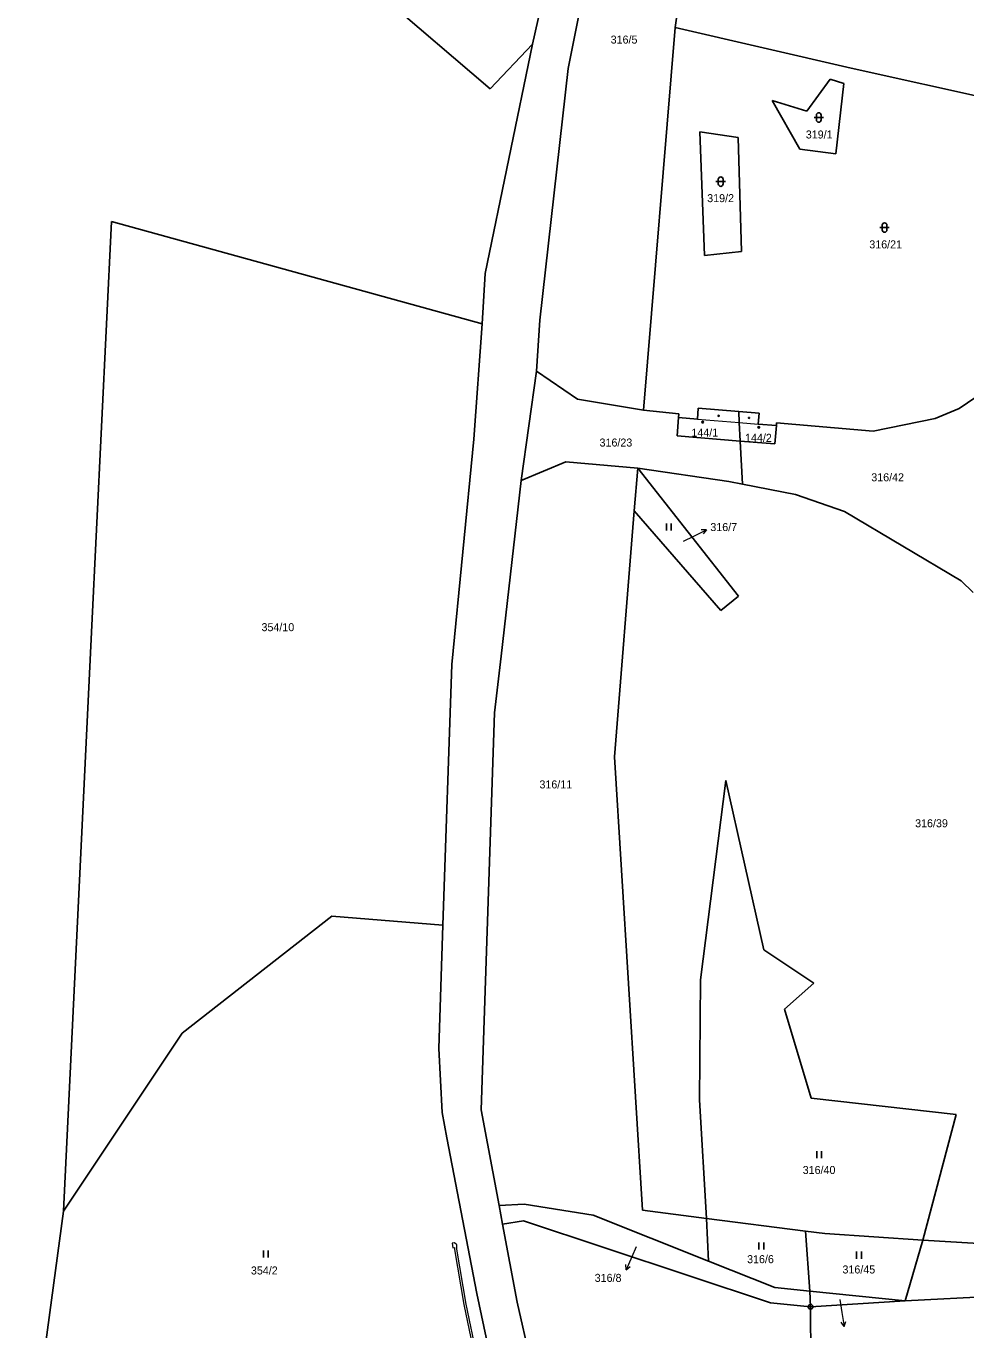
# Model space of a CAD drawing. Extents: x -765428 to -762163, y -1107632 to -1104975.
# Drawn here: x -764025.7 to -763826.2, y -1107138 to -1106861.1 of the extents above; entities that cross this region are included whole.
import ezdxf
from ezdxf.enums import TextEntityAlignment as Align

# ---------------------------------------------------------------- set-up
doc = ezdxf.new("R2010")
doc.units = 0
doc.header["$LTSCALE"] = 0.68
for name, color, linetype, lineweight in [('1', 7, 'Continuous', 25), ('13', 7, 'Continuous', 13), ('3', 7, 'Continuous', 25), ('4', 7, 'Continuous', 13), ('5', 7, 'Continuous', 25), ('7', 7, 'Continuous', 13), ('8', 7, 'Continuous', 25)]:
    doc.layers.add(name, color=color, linetype=linetype, lineweight=lineweight)
doc.layers.add('2', color=7, linetype='Continuous')

msp = doc.modelspace()

# ---------------------------------------------------------------- linework, layer by layer
at = {"layer": '1'}
for p, q in [((-763887.93, -1106861.4), (-763878.91, -1106800.35)), ((-763910.6, -1106870.13), (-763900.2, -1106816.93)), ((-763984.36, -1106825.5), (-763927.16, -1106874.4)), ((-763918.21, -1106864.97), (-763911.84, -1106836.29)), ((-763887.93, -1106861.4), (-763894.66, -1106942.69)), ((-763850.56, -1106870), (-763887.93, -1106861.4)), ((-763928.25, -1106913.64), (-763918.21, -1106864.97)), ((-763927.16, -1106874.4), (-763918.21, -1106864.97)), ((-763916.66, -1106923.52), (-763910.6, -1106870.13)), ((-763859.99, -1106879.13), (-763855, -1106872.34)), ((-763855, -1106872.34), (-763852.07, -1106873.28)), ((-763805.23, -1106880.1), (-763850.56, -1106870)), ((-763852.07, -1106873.28), (-763853.8, -1106888.22)), ((-763867.35, -1106876.88), (-763859.99, -1106879.13)), ((-763861.47, -1106887.23), (-763867.35, -1106876.88)), ((-763881.72, -1106909.85), (-763882.71, -1106883.52)), ((-763882.71, -1106883.52), (-763874.56, -1106884.77)), ((-763874.56, -1106884.77), (-763873.83, -1106908.96)), ((-763853.8, -1106888.22), (-763861.47, -1106887.23)), ((-764007.56, -1106902.63), (-764011.8, -1106989.83)), ((-764007.56, -1106902.63), (-763928.92, -1106924.36)), ((-763873.83, -1106908.96), (-763881.72, -1106909.85)), ((-763928.92, -1106924.36), (-763928.25, -1106913.64)), ((-763930.69, -1106948.85), (-763928.92, -1106924.36)), ((-763917.36, -1106934.4), (-763916.66, -1106923.52)), ((-763917.36, -1106934.4), (-763920.58, -1106957.6)), ((-763917.36, -1106934.4), (-763908.66, -1106940.29)), ((-763827.64, -1106942.32), (-763822.07, -1106938.55)), ((-763908.66, -1106940.29), (-763894.66, -1106942.69)), ((-763894.66, -1106942.69), (-763887.11, -1106943.42)), ((-763887.19, -1106944.24), (-763887.51, -1106948.1)), ((-763887.11, -1106943.42), (-763887.19, -1106944.24)), ((-763883.2, -1106944.57), (-763887.19, -1106944.24)), ((-763883.01, -1106942.25), (-763883.2, -1106944.57)), ((-763874.42, -1106942.97), (-763883.01, -1106942.25)), ((-763874.42, -1106942.97), (-763874.3, -1106945.31)), ((-763870.06, -1106943.33), (-763874.42, -1106942.97)), ((-763870.26, -1106945.65), (-763870.06, -1106943.33)), ((-763845.87, -1106947.12), (-763832.71, -1106944.44)), ((-763832.71, -1106944.44), (-763827.64, -1106942.32)), ((-763874.3, -1106945.31), (-763874.09, -1106949.21)), ((-763866.42, -1106945.95), (-763870.26, -1106945.65)), ((-763866.75, -1106949.81), (-763866.42, -1106945.95)), ((-763866.42, -1106945.95), (-763866.39, -1106945.32)), ((-763866.39, -1106945.32), (-763845.87, -1106947.12)), ((-763935.35, -1106996.66), (-763930.69, -1106948.85)), ((-763887.51, -1106948.1), (-763874.09, -1106949.21)), ((-763874.09, -1106949.21), (-763873.61, -1106958.36)), ((-763874.09, -1106949.21), (-763866.75, -1106949.81)), ((-763920.58, -1106957.6), (-763911.13, -1106953.64)), ((-763911.13, -1106953.64), (-763895.87, -1106954.97)), ((-763895.87, -1106954.97), (-763896.6, -1106964.04)), ((-763895.87, -1106954.97), (-763876.52, -1106957.78)), ((-763895.87, -1106954.97), (-763874.49, -1106982.19)), ((-763924.85, -1106994.91), (-763920.58, -1106957.6)), ((-763873.61, -1106958.36), (-763876.52, -1106957.78)), ((-763873.61, -1106958.36), (-763862.36, -1106960.58)), ((-763862.36, -1106960.58), (-763851.98, -1106964.19)), ((-763896.6, -1106964.04), (-763900.81, -1107016.28)), ((-763878.25, -1106985.17), (-763896.6, -1106964.04)), ((-763851.98, -1106964.19), (-763827.21, -1106978.88)), ((-763827.21, -1106978.88), (-763824.64, -1106981.35)), ((-763874.49, -1106982.19), (-763878.25, -1106985.17)), ((-764011.8, -1106989.83), (-764017.78, -1107112.73)), ((-763937.22, -1107052.04), (-763935.35, -1106996.66)), ((-763926.24, -1107006.92), (-763924.85, -1106994.91)), ((-763929.11, -1107091.25), (-763926.24, -1107006.92)), ((-763900.81, -1107016.28), (-763894.83, -1107112.58)), ((-763992.59, -1107074.99), (-763960.81, -1107050.1)), ((-763960.81, -1107050.1), (-763937.22, -1107052.04)), ((-763938.1, -1107078.21), (-763937.22, -1107052.04)), ((-763869.12, -1107057.24), (-763858.45, -1107064.32)), ((-763882.77, -1107089.12), (-763882.57, -1107063.6)), ((-763858.45, -1107064.32), (-763864.71, -1107069.87)), ((-763864.71, -1107069.87), (-763859.02, -1107088.76)), ((-764017.78, -1107112.73), (-763992.59, -1107074.99)), ((-763937.37, -1107091.79), (-763938.1, -1107078.21)), ((-763881.28, -1107114.32), (-763882.77, -1107089.12)), ((-763859.02, -1107088.76), (-763828.23, -1107092.25)), ((-763937.37, -1107091.79), (-763936.4, -1107097.18)), ((-763925.31, -1107111.55), (-763929.11, -1107091.25)), ((-763828.23, -1107092.25), (-763835.36, -1107118.94)), ((-763936.4, -1107097.18), (-763930.05, -1107130.21)), ((-764025.72, -1107171.67), (-764017.78, -1107112.73)), ((-763919.97, -1107111.24), (-763925.31, -1107111.55)), ((-763924.56, -1107115.5), (-763925.31, -1107111.55)), ((-763905.3, -1107113.6), (-763919.97, -1107111.24)), ((-763881.28, -1107114.32), (-763894.83, -1107112.58)), ((-763920.12, -1107114.79), (-763924.56, -1107115.5)), ((-763924.56, -1107115.5), (-763921.49, -1107132.12)), ((-763867.69, -1107132.24), (-763920.12, -1107114.79)), ((-763880.87, -1107123.35), (-763905.3, -1107113.6)), ((-763881.28, -1107114.32), (-763880.87, -1107123.35)), ((-763860.26, -1107116.98), (-763881.28, -1107114.32)), ((-763856.14, -1107117.5), (-763860.26, -1107116.98)), ((-763859.32, -1107129.72), (-763860.26, -1107116.98)), ((-763835.36, -1107118.94), (-763856.14, -1107117.5)), ((-763839.06, -1107131.83), (-763835.36, -1107118.94)), ((-763797.19, -1107121.2), (-763835.36, -1107118.94)), ((-763880.87, -1107123.35), (-763866.76, -1107128.95)), ((-763866.76, -1107128.95), (-763859.32, -1107129.72)), ((-763859.17, -1107133.06), (-763859.32, -1107129.72)), ((-763859.32, -1107129.72), (-763839.06, -1107131.83)), ((-763930.05, -1107130.21), (-763921.17, -1107171.3)), ((-763921.49, -1107132.12), (-763913.75, -1107165.7)), ((-763859.17, -1107133.06), (-763867.69, -1107132.24)), ((-763839.06, -1107131.83), (-763859.17, -1107133.06)), ((-763839.06, -1107131.83), (-763818, -1107130.74)), ((-763859.17, -1107133.06), (-763858.99, -1107159.24))]:
    msp.add_line(p, q, dxfattribs=at)
msp.add_lwpolyline([(-763882.57, -1107063.6), (-763877.13, -1107021.31), (-763869.12, -1107057.24)], dxfattribs=at)
at = {"layer": '13'}
msp.add_lwpolyline([(-763920.07, -1107191.01), (-763923.64, -1107173.12), (-763927.61, -1107154.9), (-763932.27, -1107132.51), (-763934.28, -1107120.84), (-763934.24, -1107119.94), (-763934.79, -1107119.45), (-763935.28, -1107119.54), (-763935.1, -1107120.52), (-763934.77, -1107120.46), (-763934.78, -1107120.88), (-763932.77, -1107132.61), (-763928.09, -1107155), (-763924.12, -1107173.22), (-763920.55, -1107191.11), (-763917.43, -1107205.77), (-763915.76, -1107206.11), (-763914.17, -1107206.2), (-763914.28, -1107205.69), (-763915.7, -1107205.61), (-763917.01, -1107205.35)], close=True, dxfattribs=at)
at = {"layer": '3'}
for p, q in [((-763858.421, -1106880.511), (-763856.419, -1106880.511)), ((-763857.921, -1106880.011), (-763857.921, -1106881.012)), ((-763856.919, -1106881.012), (-763856.919, -1106880.011)), ((-763879.251, -1106894.131), (-763877.249, -1106894.131)), ((-763878.751, -1106893.631), (-763878.751, -1106894.632)), ((-763877.749, -1106894.632), (-763877.749, -1106893.631)), ((-763844.461, -1106903.891), (-763842.459, -1106903.891)), ((-763843.961, -1106903.391), (-763843.961, -1106904.392)), ((-763842.959, -1106904.392), (-763842.959, -1106903.391)), ((-763889.771, -1106968.22), (-763889.771, -1106966.72)), ((-763888.77, -1106968.22), (-763888.77, -1106966.72)), ((-763857.821, -1107101.53), (-763857.821, -1107100.03)), ((-763856.82, -1107101.53), (-763856.82, -1107100.03)), ((-763975.341, -1107122.59), (-763975.341, -1107121.09)), ((-763974.34, -1107122.59), (-763974.34, -1107121.09)), ((-763870.121, -1107120.9), (-763870.121, -1107119.4)), ((-763869.12, -1107120.9), (-763869.12, -1107119.4)), ((-763849.381, -1107122.86), (-763849.381, -1107121.36)), ((-763848.38, -1107122.86), (-763848.38, -1107121.36))]:
    msp.add_line(p, q, dxfattribs=at)
for centre, start, end in [((-763857.42, -1106880.0109), 0, 180), ((-763857.42, -1106881.0109), 180, 359.98789), ((-763878.25, -1106893.6309), 0, 180), ((-763878.25, -1106894.6309), 180, 359.98789), ((-763843.46, -1106903.3909), 0, 180), ((-763843.46, -1106904.3909), 180, 359.98789)]:
    msp.add_arc(centre, 0.5, start, end, dxfattribs=at)
at = {"layer": '4'}
for p, q in [((-763883.2, -1106944.57), (-763874.3, -1106945.31)), ((-763874.3, -1106945.31), (-763870.26, -1106945.65))]:
    msp.add_line(p, q, dxfattribs=at)
at = {"layer": '5'}
for centre, radius in [((-763878.6746, -1106943.8694), 0.1172), ((-763872.2446, -1106944.3094), 0.1172), ((-763882.0768, -1106945.1992), 0.175), ((-763870.1568, -1106946.3192), 0.175)]:
    msp.add_circle(centre, radius, dxfattribs=at)
at = {"layer": '7'}
for p, q in [((-763881.296, -1106968.048), (-763882.416, -1106968.056)), ((-763898.293, -1107125.222), (-763897.44, -1107124.496)), ((-763852.031, -1107137.254), (-763851.693, -1107136.187))]:
    msp.add_line(p, q, dxfattribs=at)
for points in [[(-763886.16, -1106970.51), (-763883.97, -1106969.41), (-763881.296, -1106968.048), (-763881.961, -1106968.948)], [(-763896.21, -1107120.35), (-763897.12, -1107122.46), (-763898.293, -1107125.222), (-763898.362, -1107124.105)], [(-763852.93, -1107131.5), (-763852.5, -1107134.29), (-763852.031, -1107137.254), (-763852.682, -1107136.343)]]:
    msp.add_lwpolyline(points, dxfattribs=at)
at = {"layer": '8'}
for radius in [0.5, 0.0303]:
    msp.add_circle((-763859.17, -1107133.0599), radius, dxfattribs=at)

# ---------------------------------------------------------------- texts
at = {"layer": '2'}
for s, p in [('316/5', (-763901.61, -1106864.815)), ('319/1', (-763860.18, -1106884.965)), ('319/2', (-763881.11, -1106898.485)), ('316/21', (-763846.7, -1106908.305)), ('144/1', (-763884.47, -1106948.275)), ('316/23', (-763903.97, -1106950.385)), ('144/2', (-763873.08, -1106949.385)), ('316/42', (-763846.28, -1106957.765)), ('316/7', (-763880.45, -1106968.335)), ('354/10', (-763975.74, -1106989.595)), ('316/11', (-763916.73, -1107022.985)), ('316/39', (-763836.97, -1107031.235)), ('316/40', (-763860.84, -1107104.865)), ('354/2', (-763977.99, -1107126.205))]:
    msp.add_text(s, height=1.7, dxfattribs=at).set_placement(p)
for s, p in [('316/6', (-763869.8, -1107123.805)), ('316/45', (-763848.92, -1107125.995))]:
    msp.add_text(s, height=1.7, dxfattribs=at).set_placement(p, align=Align.CENTER)
msp.add_text('316/8', height=1.7, dxfattribs=at).set_placement((-763899.31, -1107127.775), align=Align.RIGHT)

doc.saveas('drawing.dxf')
